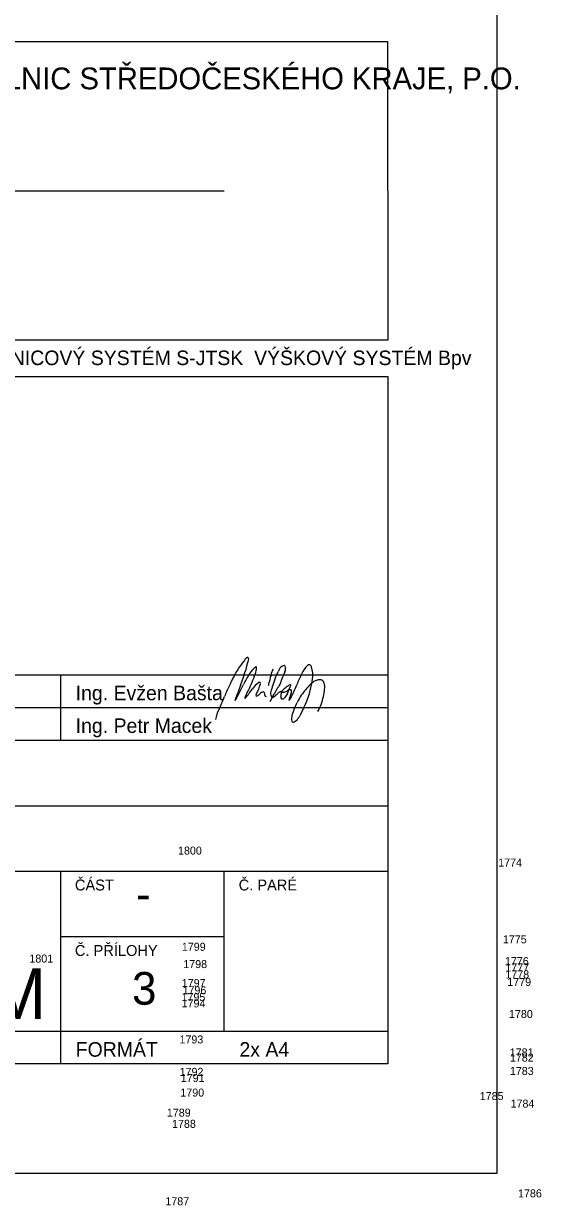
# Model space of a CAD drawing. Extents: x -740053 to -737517, y -1033516 to -1032465.
# Drawn here: x -738098 to -738062.5, y -1032615.4 to -1032534.2 of the extents above; entities that cross this region are included whole.
import ezdxf

# ---------------------------------------------------------------- set-up
doc = ezdxf.new("R2010")
doc.units = 0
for name, color, linetype in [('_MIKA', 7, 'Continuous'), ('bod-cislo', 7, 'Continuous'), ('promika-formát', 7, 'Continuous'), ('promika-rozp', 7, 'Continuous'), ('promika-rozp-text-firmy', 7, 'Continuous')]:
    doc.layers.add(name, color=color, linetype=linetype)

msp = doc.modelspace()

# ---------------------------------------------------------------- linework, layer by layer
at = {"layer": '_MIKA'}
msp.add_lwpolyline([(-738081.091, -1032580.804), (-738080.802, -1032580.278)], dxfattribs=at)
for centre, radius, start, end in [((-738077.208, -1032582.43), 7.198, 142.23523, 153.41785), ((-738064.501, -1032592.274), 23.272, 141.62525, 142.23523), ((-738068.424, -1032581.843), 14.699, 164.31686, 167.58851), ((-738082.653, -1032577.901), 0.119, 77.65258, 141.62525), ((-738082.642, -1032577.851), 0.068, 344.31686, 77.65258), ((-738124.931, -1032564.713), 44.406, 340.28609, 341.66347), ((-738076.794, -1032582.56), 6.785, 146.97351, 154.45028), ((-738091.884, -1032575.493), 10.355, 333.90134, 340.8079), ((-738080.785, -1032579.965), 2.025, 132.28695, 146.97351), ((-738082.068, -1032578.534), 0.104, 95.68301, 139.83775), ((-738083.504, -1032578.407), 1.483, 340.68391, 357.12395), ((-738082.066, -1032578.473), 0.0444, 349.81416, 105.49835), ((-738081.752, -1032578.748), 0.767, 337.07897, 353.18058), ((-738080.525, -1032578.895), 0.468, 139.22083, 173.18058), ((-738084.859, -1032576.969), 4.673, 332.41674, 338.14258), ((-738079.716, -1032579.032), 0.869, 143.70851, 158.14258), ((-737924.765, -1032641.138), 167.377, 158.12382, 158.43787), ((-738080.034, -1032578.799), 0.474, 99.82381, 143.70851), ((-738080.152, -1032578.456), 0.13, 357.13165, 73.63723), ((-738080.98, -1032578.415), 0.96, 338.12382, 357.13165), ((-738073.06, -1032581.963), 6.616, 152.29875, 159.50378), ((-738076.375, -1032580.222), 2.872, 139.05622, 152.29875), ((-738078.414, -1032578.453), 0.173, 15.21404, 139.05622), ((-738080.06, -1032578.984), 1.902, 351.39073, 17.62988), ((-738076.857, -1032583.223), 7.866, 153.77616, 159.46538), ((-737997.669, -1032622.23), 96.139, 153.41785, 153.77616), ((-738099.551, -1032571.681), 18.439, 330.61841, 334.45028), ((-738062.131, -1032587.216), 22.304, 160.28609, 161.69166), ((-738080.776, -1032581.035), 1.885, 124.89597, 145.05699), ((-738076.473, -1032581.806), 5.731, 157.76834, 162.23546), ((-738081.81, -1032579.553), 0.0779, 55.10403, 124.89597), ((-738082.01, -1032579.543), 0.25, 337.76834, 12.42518), ((-738078.117, -1032580.279), 3.146, 165.90811, 169.54357), ((-738061.714, -1032584.397), 20.058, 164.53011, 165.90811), ((-738066.718, -1032584.115), 14.867, 162.64406, 164.43328), ((-738072.522, -1032582.301), 8.786, 158.86527, 162.64406), ((-738062.014, -1032590.59), 21.433, 149.22929, 151.24035), ((-738078.352, -1032581.952), 2.686, 125.81479, 133.21132), ((-738078.669, -1032581.512), 2.144, 119.74147, 125.81479), ((-738093.482, -1032574.269), 14.839, 336.22301, 338.12374), ((-738079.712, -1032579.686), 0.0415, 339.1031, 119.74147), ((-738085.398, -1032577.515), 6.128, 338.12374, 339.1031), ((-738085.69, -1032577.241), 6.867, 335.01458, 339.50378), ((-738073.77, -1032584.088), 6.376, 135.47239, 144.29948), ((-738085.793, -1032578.116), 7.701, 342.2433, 351.39073), ((-738077.512, -1032580.407), 1.128, 115.27288, 135.47239), ((-738077.647, -1032580.121), 0.811, 93.24087, 115.27288), ((-738077.675, -1032579.62), 0.309, 16.61177, 93.24087), ((-738078.362, -1032579.825), 1.026, 352.45357, 16.61177), ((-738093.598, -1032576.952), 10.012, 334.10342, 339.46538), ((-738104.481, -1032573.203), 22.304, 340.28609, 341.69166), ((-738082.558, -1032580.57), 0.266, 150.33743, 175.43081), ((-738082.801, -1032580.551), 0.0218, 175.43081, 341.96748), ((-738088.03, -1032577.454), 6.032, 330.33743, 334.51836), ((-738089.934, -1032574.636), 9.287, 320.38725, 325.05699), ((-738081.918, -1032580.358), 0.143, 157.34282, 210.29061), ((-738079.742, -1032581.266), 2.501, 151.08165, 157.34281), ((-738082.06, -1032580.165), 0.266, 274.06523, 322.04071), ((-738081.439, -1032580.65), 0.522, 109.96924, 142.04071), ((-738081.568, -1032580.242), 0.0966, 16.46783, 120.57707), ((-738082.942, -1032580.483), 1.491, 4.64701, 10.37671), ((-738081.364, -1032580.364), 0.0917, 178.87234, 265.72159), ((-738080.555, -1032580.26), 0.503, 164.43328, 200.27708), ((-738080.92, -1032580.395), 0.115, 200.27708, 295.62005), ((-738082.361, -1032578.388), 2.584, 305.25171, 313.28111), ((-738079.785, -1032581.124), 1.174, 123.9927, 133.28111), ((-738080.384, -1032580.199), 0.0751, 330.79764, 140.06184), ((-738080.182, -1032580.499), 0.174, 168.44211, 226.63633), ((-738082.433, -1032580.039), 2.124, 348.4421, 354.69045), ((-738080.259, -1032580.419), 0.211, 258.27689, 327.55364), ((-738080.243, -1032580.115), 0.0443, 160.07678, 271.04324), ((-738080.164, -1032580.143), 0.128, 132.49991, 160.07678), ((-738084.66, -1032575.236), 6.527, 312.49991, 313.21132), ((-738080.263, -1032579.036), 1.123, 271.04324, 277.1213), ((-738080.173, -1032579.754), 0.4, 277.1213, 296.25137), ((-737905.684, -1032691.406), 206.658, 147.46165, 147.55364), ((-738080.212, -1032579.674), 0.489, 296.25137, 309.92826), ((-738079.669, -1032580.323), 0.357, 114.58049, 129.92826), ((-738079.739, -1032580.169), 0.188, 88.02122, 114.58049), ((-738078.608, -1032580.993), 1.216, 161.13101, 166.95348), ((-738080.816, -1032579.889), 1.33, 321.43729, 335.0016), ((-738080.909, -1032580.207), 1.216, 341.13101, 346.95348), ((-738079.74, -1032580.192), 0.211, 61.49258, 88.02122), ((-738079.049, -1032580.638), 0.693, 155.07666, 166.95348), ((-738080.242, -1032580.083), 0.622, 335.07666, 354.59191), ((-738079.936, -1032580.112), 0.315, 354.59191, 19.66909), ((-739445.965, -1031943.356), 1507.586, 335.001598, 335.014577), ((-738076.665, -1032582.007), 2.811, 144.29948, 156.17031), ((-738083.356, -1032578.896), 5.141, 333.88055, 342.2433), ((-738080.845, -1032579.766), 3.487, 330.20089, 348.45026), ((-738084.606, -1032578.998), 7.325, 348.45026, 352.45357), ((-738082.921, -1032582.285), 1.927, 150.11086, 172.99111), ((-738079.784, -1032580.721), 0.00871, 166.95348, 13.04652), ((-738077.41, -1032582.239), 2.232, 154.16547, 167.44743), ((-738090.596, -1032575.854), 12.418, 334.16547, 336.17031), ((-734824.907, -1034176.566), 3623.913, 153.880552, 153.891528), ((-738078.725, -1032581.976), 0.892, 165.54134, 191.72704), ((-738079.495, -1032582.11), 0.114, 204.62312, 301.34548), ((-738079.709, -1032581.647), 0.623, 296.02507, 312.0858), ((-738080.016, -1032581.307), 1.081, 312.0858, 333.89153)]:
    msp.add_arc(centre, radius, start, end, dxfattribs=at)
at = {"layer": 'promika-formát'}
msp.add_lwpolyline([(-738170.499, -1032613.213), (-738065.499, -1032613.213), (-738065.499, -1032464.713), (-738170.499, -1032464.713)], close=True, dxfattribs=at)
at = {"layer": 'promika-rozp'}
for p, q in [((-738162.999, -1032578.963), (-738072.999, -1032578.963)), ((-738095.499, -1032578.963), (-738095.499, -1032583.463)), ((-738162.999, -1032581.213), (-738072.999, -1032581.213)), ((-738162.999, -1032583.463), (-738072.999, -1032583.463)), ((-738162.999, -1032587.963), (-738072.999, -1032587.963)), ((-738162.999, -1032592.463), (-738072.999, -1032592.463)), ((-738095.499, -1032592.463), (-738095.499, -1032605.713)), ((-738084.249, -1032603.463), (-738084.249, -1032592.463)), ((-738095.499, -1032596.963), (-738084.249, -1032596.963)), ((-738162.999, -1032603.463), (-738072.999, -1032603.463))]:
    msp.add_line(p, q, dxfattribs=at)
for points in [[(-738072.999, -1032545.713), (-738072.999, -1032535.463), (-738162.999, -1032535.463), (-738162.999, -1032545.713)], [(-738072.999, -1032545.713), (-738072.999, -1032555.963), (-738162.999, -1032555.963), (-738162.999, -1032545.713)], [(-738130.823, -1032545.713), (-738084.249, -1032545.713)], [(-738162.999, -1032578.963), (-738162.999, -1032558.463), (-738072.999, -1032558.463), (-738072.999, -1032578.963)], [(-738072.999, -1032578.963), (-738072.999, -1032605.713), (-738162.999, -1032605.713), (-738162.999, -1032578.963)], [(-738162.999, -1032583.463), (-738072.999, -1032583.463)]]:
    msp.add_lwpolyline(points, dxfattribs=at)

# ---------------------------------------------------------------- texts
at = {"layer": 'bod-cislo'}
for s, p in [('1800', (-738087.418, -1032591.323)), ('1774', (-738065.421, -1032592.143)), ('1799', (-738087.155, -1032597.933)), ('1775', (-738065.098, -1032597.423)), ('1801', (-738097.63, -1032598.743)), ('1776', (-738064.958, -1032598.923)), ('1798', (-738087.058, -1032599.123)), ('1777', (-738064.928, -1032599.353)), ('1778', (-738064.928, -1032599.833)), ('1797', (-738087.158, -1032600.423)), ('1779', (-738064.795, -1032600.353)), ('1795', (-738087.178, -1032601.393)), ('1796', (-738087.108, -1032600.923)), ('1794', (-738087.171, -1032601.823)), ('1780', (-738064.678, -1032602.553)), ('1793', (-738087.318, -1032604.303)), ('1781', (-738064.63, -1032605.193)), ('1782', (-738064.618, -1032605.553)), ('1792', (-738087.308, -1032606.533)), ('1791', (-738087.23, -1032606.953)), ('1783', (-738064.618, -1032606.473)), ('1790', (-738087.258, -1032607.953)), ('1785', (-738066.688, -1032608.193)), ('1784', (-738064.571, -1032608.713)), ('1789', (-738088.185, -1032609.333)), ('1788', (-738087.828, -1032610.103)), ('1786', (-738064.058, -1032614.883)), ('1787', (-738088.288, -1032615.423))]:
    msp.add_text(s, height=0.55, dxfattribs=at).set_placement(p)
at = {"layer": 'promika-rozp'}
for s, height, p in [('SOUŘADNICOVÝ SYSTÉM S-JTSK  VÝŠKOVÝ SYSTÉM Bpv', 1, (-738104.631, -1032557.682)), ('Ing. Evžen Bašta', 1, (-738094.448, -1032580.713)), ('Ing. Petr Macek', 1, (-738094.448, -1032582.963)), ('ČÁST', 0.75, (-738094.501, -1032593.789)), ('Č. PARÉ', 0.75, (-738083.251, -1032593.789)), ('-', 2.25, (-738090.293, -1032595.141)), ('Č. PŘÍLOHY', 0.75, (-738094.501, -1032598.289)), ('3', 2.25, (-738090.573, -1032601.641)), ('FORMÁT', 1, (-738094.448, -1032605.213)), ('2x A4', 1, (-738083.198, -1032605.213))]:
    msp.add_text(s, height=height, dxfattribs=at).set_placement(p)
at = {"layer": 'promika-rozp-text-firmy'}
for s, height, p in [('KRAJSKÁ SPRÁVA A ÚDRŽBA SILNIC STŘEDOČESKÉHO KRAJE, P.O.', 1.5, (-738130.303, -1032538.728)), ('DENDROLOGICKÝ PRŮZKUM', 3.5, (-738162.001, -1032602.632))]:
    msp.add_text(s, height=height, dxfattribs=at).set_placement(p)

doc.saveas('drawing.dxf')
